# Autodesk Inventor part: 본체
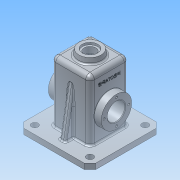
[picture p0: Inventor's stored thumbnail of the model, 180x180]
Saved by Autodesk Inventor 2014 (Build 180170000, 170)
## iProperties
Created: 2016-02
Part Number: 본체
Material: 알루미늄 6061
Document SubType Name: Modeling
Designer: nert
Density: 2.71 g/cm^3
Appearance: 알루미늄 - 평지
Mass: 937.564 g
Surface Area: 1047.05 cm^2
Volume: 345.965 cm^3
Author: nert
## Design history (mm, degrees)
sketch "스케치1"
  geometry: L1 (65, -65)-(-65, -65); L2 (-65, -65)-(-65, 65); L3 (-65, 65)-(65, 65); L4 (65, 65)-(65, -65); L5 (65, -65)-(-65, 65); L6 (-65, -65)-(65, 65); 1 further point
  constraints: 12 end point, 2 midpoint, 2 parallel, 1 horizontal, 1 perpendicular
  dimensions: "d0" = 130 distance of L1.start L1.end; "d1" = 130 distance of L1.end L2.end
extrude "돌출1" new body sketch "스케치1" distance "d2" = 10; taper "d3" = 0 deg
node "작업 평면1"
sketch "스케치2"
  geometry: L1 (65, 0)-(65, 55); C1 r 27.5 at (65, 55)
  constraints: 2 end point, 1 centre point, 1 coincident, 1 vertical
  dimensions: "d4" = 55 distance of L1.start L1.end; "d5" = 55 diameter of C1
extrude "돌출2" join sketch "스케치2" stored distance "d6" = 96; taper "d7" = 0 deg
sketch "스케치3"
  geometry: C1 r 27.5 at (0, 0) reference; C2 r 16 at (0, 0); 1 further point
  constraints: 1 centre point, 1 coincident
  dimensions: "d8" = 32 diameter of C2
sketch "스케치4"
  geometry: L1 (-35, 35)-(35, 35); L2 (35, 35)-(35, -35); L3 (35, -35)-(-35, -35); L4 (-35, -35)-(-35, 35); L5 (-35, 35)-(35, -35); L6 (35, 35)-(-35, -35); 1 further point
  constraints: 12 end point, 2 midpoint, 2 parallel, 1 horizontal, 1 perpendicular
  dimensions: "d9" = 70 distance of L2.end L3.end; "d10" = 70 distance of L1.end L2.end
extrude "돌출3" join sketch "스케치4" distance "d11" = 110; taper "d12" = 0 deg
fillet "모깎기1" dims "d13" = 8
node "작업 평면2"
sketch "스케치5"
  geometry: C1 r 20 at (0, 0); 1 further point
  constraints: 1 centre point, 1 coincident
  dimensions: "d15" = 40 diameter of C1
extrude "돌출4" join sketch "스케치5" stored distance "d16" = 110; taper "d17" = 0 deg
node "작업 평면3"
node "작업 평면4"
sketch "스케치6"
  geometry: L1 (92, 120)-(38, 120) reference; L2 (85, 130)-(85, 120) reference; L3 (85, 130)-(86.763, 120); L4 (86.763, 120)-(85, 120); L5 (85, 120)-(85, 130); L6 (65, 120)-(65, 130); 1 further point
  constraints: 8 end point, 2 equal length, 1 midpoint, 1 point on line
  dimensions: "d19" = 80 deg angle of L1 L3
revolve "회전1" sketch "스케치6" stored, may be unused: angle "d20" = 90 deg
sketch "스케치7"
  geometry: C1 r 20 at (0, 0) reference; C2 r 14 at (0, 0)
  constraints: 1 centre point, 1 coincident
  dimensions: "d21" = 28 diameter of C2
extrude "돌출5" cut sketch "스케치7" distance "d22" = 4; taper "d23" = 0 deg
sketch "스케치8"
  geometry: C1 r 14 at (0, 0) reference; C2 r 10.5 at (0, 0)
  constraints: 1 centre point, 1 coincident
  dimensions: "d24" = 21 diameter of C2
extrude "돌출6" cut sketch "스케치8" stored distance "d25" = 4; taper "d26" = 0 deg
extrude "돌출7" cut sketch "스케치3" stored distance "d27" = 4; taper "d28" = 0 deg
sketch "스케치9"
  geometry: L1 (-30, 30)-(30, 30); L2 (30, 30)-(30, -30); L3 (30, -30)-(-30, -30); L4 (-30, -30)-(-30, 30); L5 (-30, 30)-(30, -30); L6 (30, 30)-(-30, -30); C1 r 10.5 at (0, 0) reference
  constraints: 12 end point, 2 midpoint, 2 parallel, 1 horizontal, 1 perpendicular
  dimensions: "d29" = 60 distance of L1.end L2.end; "d30" = 60 distance of L1.start L1.end
extrude "돌출8" cut sketch "스케치9" distance "d31" = 115; taper "d32" = 0 deg
fillet "모깎기2" dims "d33" = 8
fillet "모깎기3" dims "d34" = 3
chamfer "모따기1" distance "d35" = 1; stored, may be unused: second distance "d36" = 2, angle "d37" = 45 deg
sketch "스케치10"
  geometry: L1 (35, 0)-(35, 115) reference; L2 (30, 60.22)-(30, 112) reference; L3 (113, 38)-(113, 72) reference; L4 (113, 55)-(-10.692, 55); L5 (113, 82.5)-(-10.692, 82.5); L6 (17, 82.5)-(17, 27.5) reference; L7 (30, 49.78)-(30, 49.78) reference; L8 (30, 60.22)-(30, 60.22) reference; L9 (35, 71)-(18, 71) reference; L10 (35, 39)-(18, 39) reference; L11 (112, 71)-(95, 71) reference; L12 (100, 49.78)-(100, 49.78) reference; L13 (100, 60.22)-(100, 60.22) reference; L14 (113, 27.5)-(113, 82.5) reference; L15 (112, 39)-(95, 39) reference; L16 (35, 82.5)-(42, 75.5); L17 (35, 71)-(42, 71); L18 (35, 71)-(35, 82.5); L19 (65, 130.098)-(65, 0); L20 (42, 0)-(42, 39); L21 (42, 71)-(42, 75.5); L22 (95, 82.5)-(88, 75.5); L23 (88, 71)-(88, 75.5); L24 (95, 71)-(88, 71); L25 (95, 71)-(95, 82.5)
  constraints: 24 end point, 4 parallel, 4 perpendicular, 4 vertical alignment, 3 point on line, 3 symmetric about line, 1 midpoint
  dimensions: "d39" = 27.5 distance between parallel lines of L5 L4; "d43" = 4.5 distance of L17.end L16.end; "d44" = 7 distance between parallel lines of L18 L21
  node "투영된 루프1"
  node "투영된 루프2"
fillet "모깎기4" dims "d41" = 3
fillet "모깎기5" dims "d42" = 3
revolve "회전2" stored, may be unused: angle "d45" = 90 deg
revolve "회전3" stored, may be unused: angle "d46" = 90 deg
sketch "스케치11"
  geometry: 1 further point
sketch "스케치12"
  geometry: L1 (0, 0)-(0, 10) reference; L2 (130, 0)-(0, 0) reference; L3 (0, 10)-(15, 10); L4 (15, 10)-(30, 95.069); L5 (30, 112)-(30, 10) reference; L6 (30, 95.069)-(30, 10); L7 (30, 10)-(15, 10); 1 further point
  constraints: 8 end point, 1 collinear, 1 parallel, 1 perpendicular, 1 point on line
  dimensions: "d47" = 15 distance of L1.end L3.end; "d48" = 100 deg angle of L3 L4
extrude "돌출9" join sketch "스케치12" stored distance "d49" = 10; taper "d50" = 0 deg
fillet "모깎기6" dims "d51" = 0.5
fillet "모깎기7" dims "d52" = 0.5
fillet "모깎기8" dims "d53" = 0.5
fillet "모깎기9" dims "d54" = 0.5
fillet "모깎기10" dims "d55" = 3
fillet "모깎기11" dims "d56" = 3
fillet "모깎기12" dims "d57" = 3
chamfer "모따기2" distance "d58" = 10; stored, may be unused: second distance "d59" = 2, angle "d60" = 45 deg
sketch "스케치13" dims "d61" = 45
  geometry: L1 (0, 0)-(0, 22.5); C1 r 17 at (0, 0) reference; 1 further point
  constraints: 2 end point, 1 coincident, 1 vertical, 1 vertical alignment, 2 other
hole "구멍1" sketch "스케치13" at (0, 22.5) diameter "d62" = 4; stored, may be unused: countersink angle "d66" = 90 deg, drill point angle "d68" = 118 deg; dims "d63" = 6, "d64" = 4, "d65" = 2, "d67" = 10
feature "스레드1" dims "d69" = 8, "d70" = 0
sketch "스케치14" dims "d74" = 45
  geometry: L1 (0, 0)-(0, 22.5); C1 r 17 at (0, 0) reference; 1 further point
  constraints: 2 end point, 1 coincident, 1 vertical, 1 vertical alignment, 2 other
hole "구멍2" sketch "스케치14" at (0, 22.5) diameter "d75" = 4; stored, may be unused: countersink angle "d79" = 90 deg, drill point angle "d81" = 118 deg; dims "d76" = 6, "d77" = 4, "d78" = 2, "d80" = 10
feature "스레드2" dims "d82" = 8, "d83" = 0
sketch "스케치15"
  geometry: L1 (-65, 55)-(-55, 65) reference; L2 (-65, 55)-(-65, -55) reference; L3 (-55, -65)-(-65, -55) reference; L4 (-55, -65)-(55, -65) reference; L5 (65, -55)-(55, -65) reference; L6 (65, -55)-(65, 55) reference; L7 (55, 65)-(65, 55) reference; L8 (55, 65)-(-55, 65) reference; L9 (27, 38)-(8, 38) reference; L10 (38, -27)-(38, 27) reference; L11 (8, -38)-(27, -38) reference; L12 (8, -46.425)-(8, -38) reference; L13 (-2, -52.517)-(2, -52.517) reference; L14 (-8, -38)-(-8, -46.425) reference; L15 (-27, -38)-(-8, -38) reference; L16 (-38, 27)-(-38, -27) reference; L17 (-8, 38)-(-27, 38) reference; L18 (-8, 46.425)-(-8, 38) reference; L19 (2, 52.517)-(-2, 52.517) reference; L20 (8, 38)-(8, 46.425) reference; A1 r 11 centre (27, 27) between (38, 27) and (27, 38) reference; A2 r 11 centre (27, -27) between (27, -38) and (38, -27) reference; A3 r 11 centre (-27, -27) between (-38, -27) and (-27, -38) reference; A4 r 11 centre (-27, 27) between (-27, 38) and (-38, 27) reference; 5 further points; 4 other entities
  constraints: 4 other
hole "구멍3" diameter "d89" = 12; stored, may be unused: countersink angle "d93" = 90 deg, drill point angle "d95" = 118 deg; dims "d87" = 15, "d88" = 15, "d90" = 6, "d91" = 4, "d92" = 2, "d94" = 10
hole "구멍4" diameter "d98" = 12; stored, may be unused: countersink angle "d102" = 90 deg, drill point angle "d104" = 118 deg; dims "d96" = 15, "d97" = 15, "d99" = 6, "d100" = 4, "d101" = 2, "d103" = 10
hole "구멍5" diameter "d107" = 12; stored, may be unused: countersink angle "d111" = 90 deg, drill point angle "d113" = 118 deg; dims "d105" = 15, "d106" = 15, "d108" = 6, "d109" = 4, "d110" = 2, "d112" = 10
hole "구멍6" diameter "d116" = 12; stored, may be unused: countersink angle "d120" = 90 deg, drill point angle "d122" = 118 deg; dims "d114" = 15, "d115" = 15, "d117" = 6, "d118" = 4, "d119" = 2, "d121" = 10
sketch "스케치16"
  geometry: L1 (-20, 75)-(20, 75) reference; L2 (35, -42)-(35, 57) reference; 2 further points
  constraints: 1 other
  dimensions: "d123" = 35 distance from line of L2 point (0, 45); "d124" = 30 distance from line of L1 point (0, 45)
feature "엠보싱1" sketch "스케치16" dims "d125" = 0.5, "d126" = 0
sketch "스케치17"
  geometry: 1 further point
fillet "모깎기13" dims "d127" = 0.5
node "작업 평면5"
node "솔리드1"
mirror "대칭1"
pattern_circular "원형 패턴1" dims angle "d72" = 360 deg
pattern_circular "원형 패턴2" dims angle "d85" = 360 deg
other parameters: "d38" = 7, "d40" = 135 deg
